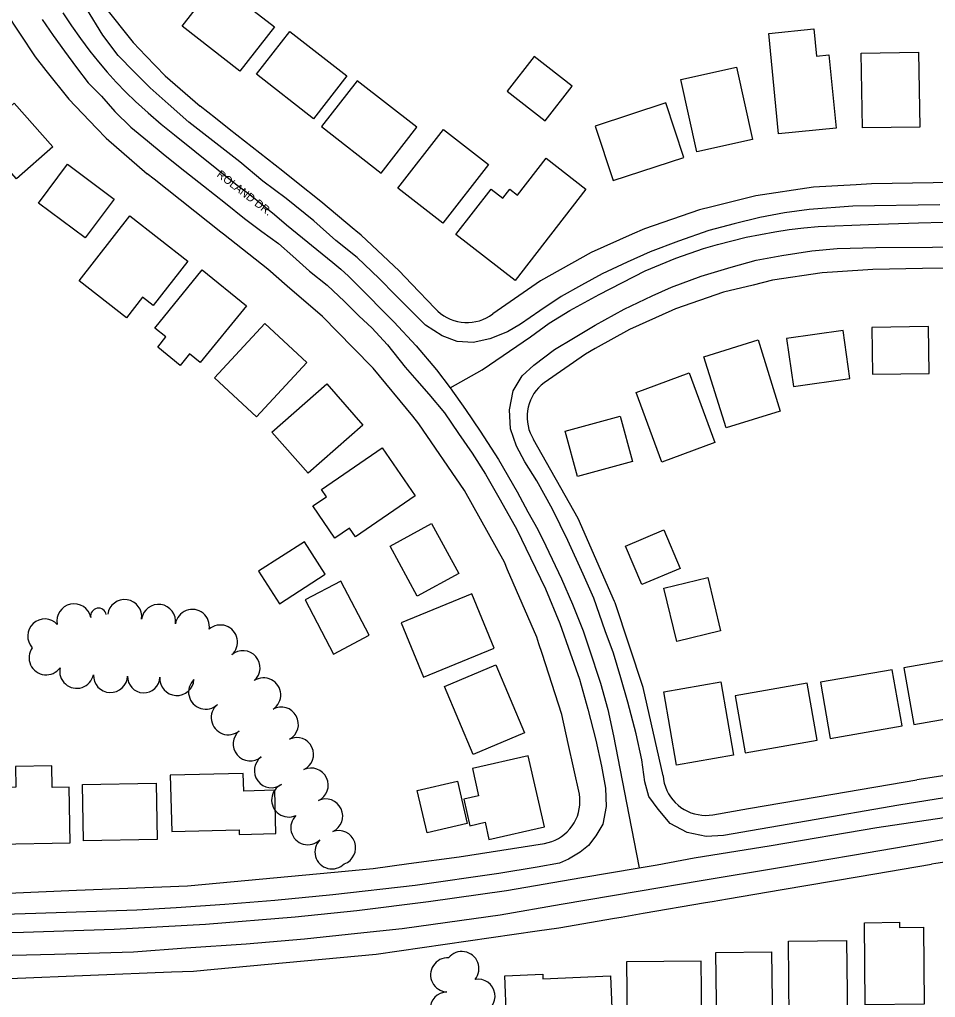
# Model space of a CAD drawing. Extents: x -2233 to 187241, y 4582 to 150524.
# Drawn here: x 115091 to 115627, y 58418 to 58990 of the extents above; entities that cross this region are included whole.
import ezdxf

# ---------------------------------------------------------------- set-up
doc = ezdxf.new("R2010")
doc.units = 0
for name, color, linetype in [('BLDG', 7, 'Continuous'), ('GE_X_CL_2000', 7, 'Continuous'), ('ROAD', 7, 'Continuous'), ('ROAD-NAME', 7, 'Continuous'), ('RW_X_Fee_RW', 7, 'Continuous'), ('TREES', 7, 'Continuous')]:
    doc.layers.add(name, color=color, linetype=linetype)

msp = doc.modelspace()

# ---------------------------------------------------------------- linework, layer by layer
at = {"layer": 'BLDG'}
for points in [[(115239.82, 58985.62), (115219.64, 58959.69), (115185.78, 58986.06), (115205.95, 59011.98)], [(115248.89, 58983.02), (115282.32, 58956.99), (115262.8, 58931.93), (115229.38, 58957.96)], [(115555.55, 58984.46), (115557.1, 58968.53), (115564.32, 58969.23), (115568.47, 58926.41), (115534.78, 58923.14), (115529.08, 58981.89)], [(115616.75, 58970.91), (115617.49, 58927.11), (115583.95, 58926.54), (115583.2, 58970.34)], [(115376.08, 58948.07), (115398.32, 58930.75), (115414.09, 58951.02), (115391.85, 58968.32)], [(115510.2, 58962.09), (115519.51, 58919.87), (115486.94, 58912.68), (115477.63, 58954.91)], [(115267.47, 58927.32), (115302.32, 58900.18), (115323.2, 58927), (115288.34, 58954.14)], [(115087.53, 58941.08), (115110.12, 58915.54), (115088.9, 58896.76), (115066.3, 58922.29)], [(115438.09, 58895.74), (115479.48, 58909.37), (115468.98, 58941.27), (115427.59, 58927.64)], [(115365.14, 58905.14), (115338.47, 58870.86), (115312.15, 58891.36), (115338.82, 58925.63)], [(115366.69, 58890.72), (115373.49, 58885.42), (115377.65, 58890.75), (115382.07, 58887.31), (115398.85, 58908.86), (115422.16, 58890.72), (115380.64, 58837.39), (115346.1, 58864.28)], [(115118.81, 58905.33), (115146.02, 58885), (115129.05, 58862.28), (115101.84, 58882.61)], [(115189.2, 58848.73), (115168.92, 58822.69), (115162.75, 58827.5), (115153.35, 58815.43), (115125.53, 58837.08), (115155.21, 58875.2)], [(115223.43, 58822.59), (115196.44, 58789.29), (115190.07, 58794.45), (115184.61, 58787.71), (115171.54, 58798.31), (115176.39, 58804.31), (115169.96, 58809.52), (115197.55, 58843.56)], [(115258.84, 58789.4), (115229.37, 58757.62), (115204.74, 58780.45), (115234.21, 58812.23)], [(115589.88, 58782.46), (115623.03, 58783.02), (115622.56, 58810.49), (115589.41, 58809.92)], [(115543.51, 58775.3), (115576.57, 58780.01), (115572.57, 58808.12), (115539.51, 58803.42)], [(115522.93, 58802.64), (115535.87, 58760.98), (115504.1, 58751.12), (115491.17, 58792.78)], [(115482.47, 58783.33), (115497.53, 58742.49), (115466.54, 58731.07), (115451.48, 58771.9)], [(115291.66, 58752.75), (115259.61, 58724.56), (115238.42, 58748.66), (115270.47, 58776.85)], [(115449.37, 58731.5), (115417.25, 58722.66), (115409.96, 58749.13), (115442.09, 58757.97)], [(115322.18, 58711.37), (115287.28, 58687.48), (115283.8, 58692.55), (115275.28, 58686.72), (115262.43, 58705.48), (115270.32, 58710.88), (115267.39, 58715.16), (115302.94, 58739.49)], [(115331.84, 58695.2), (115347.79, 58665.92), (115323.46, 58652.66), (115307.51, 58681.95)], [(115467.72, 58691.5), (115477.29, 58668.97), (115454.86, 58659.43), (115445.28, 58681.96)], [(115242.86, 58648.3), (115269.61, 58665.5), (115257.36, 58684.55), (115230.61, 58667.36)], [(115295.3, 58629.82), (115278.7, 58661.53), (115257.77, 58650.57), (115274.38, 58618.86)], [(115493.38, 58663.54), (115500.91, 58632.35), (115475.33, 58626.18), (115467.8, 58657.35)], [(115327.11, 58605.33), (115368.39, 58622.26), (115355.38, 58653.99), (115314.11, 58637.08)], [(115614.04, 58577.71), (115656.35, 58585.13), (115650.54, 58618.26), (115608.22, 58610.84)], [(115369.43, 58612.57), (115386.19, 58572.84), (115356.09, 58560.15), (115339.34, 58599.87)], [(115565.14, 58569.45), (115607.12, 58576.82), (115601.35, 58609.68), (115559.37, 58602.31)], [(115500.99, 58602.53), (115508.48, 58559.8), (115475.17, 58553.95), (115467.67, 58596.69)], [(115515.23, 58561.09), (115557.43, 58568.5), (115551.6, 58601.74), (115509.4, 58594.34)], [(115355.67, 58551.95), (115359.32, 58535.91), (115350.73, 58533.96), (115354.27, 58518.42), (115363.12, 58520.44), (115365.41, 58510.36), (115397.82, 58517.73), (115388.34, 58559.39)], [(115120.38, 58508.44), (115119.81, 58541.05), (115109.78, 58540.88), (115109.56, 58553.4), (115088.41, 58553.03), (115088.63, 58540.9), (115077.21, 58540.7), (115077.8, 58507.69)], [(115219.18, 58516.01), (115219.25, 58513.39), (115240.78, 58513.95), (115240.12, 58539.21), (115221.92, 58538.74), (115221.65, 58549.04), (115178.89, 58547.93), (115179.75, 58514.99)], [(115127.48, 58542.57), (115170.68, 58543.34), (115171.27, 58510.32), (115128.06, 58509.56)], [(115346.91, 58544.52), (115352.61, 58519.69), (115329.15, 58514.31), (115323.46, 58539.13)], [(115605.58, 58461.94), (115605.62, 58458.88), (115619.62, 58459.02), (115620.11, 58414.03), (115585.62, 58413.66), (115585.1, 58461.71)], [(115574.6, 58451.33), (115575.1, 58405.8), (115571.61, 58405.76), (115571.7, 58397.2), (115552.57, 58396.99), (115552.49, 58405.82), (115541.14, 58405.7), (115540.65, 58450.96)], [(115530.8, 58444.62), (115531.26, 58401.58), (115498.68, 58401.22), (115498.22, 58444.26)], [(115446.23, 58404.35), (115490, 58404.82), (115489.63, 58439.24), (115445.86, 58438.75)], [(115374.6, 58430.6), (115396.89, 58431.57), (115397, 58428.94), (115436.49, 58430.64), (115437.9, 58397.63), (115394.31, 58395.76), (115393.85, 58406.47), (115375.67, 58405.69)]]:
    msp.add_lwpolyline(points, close=True, dxfattribs=at)
at = {"layer": 'GE_X_CL_2000'}
for points in [[(115116.04, 58993.83), (115121.11, 58986.23), (115126.41, 58978.79), (115131.94, 58971.53), (115136.86, 58965.26), (115142, 58959.17), (115147.33, 58953.26), (115152.87, 58947.53), (115158.59, 58942), (115166.05, 58935.34), (115173.65, 58928.83), (115181.38, 58922.48), (115218.03, 58893.18), (115225.46, 58887.59), (115232.76, 58881.84), (115239.92, 58875.92), (115246.95, 58869.85), (115274.07, 58847.9), (115278.71, 58843.95), (115283.21, 58839.82), (115287.54, 58835.53), (115309.78, 58813.14), (115322.84, 58799.11), (115334.78, 58785.1), (115342.76, 58774.57)], [(115342.76, 58774.57), (115361.42, 58785.09), (115389.78, 58804.42), (115400.59, 58812.3), (115412.74, 58819.81), (115429.91, 58829.13), (115456.89, 58842.96), (115474.81, 58850.44), (115491, 58855.99), (115499.21, 58858.43), (115507.48, 58860.63), (115515.82, 58862.59), (115524.2, 58864.33), (115532.63, 58865.82), (115541.1, 58867.08), (115549.6, 58868.1), (115558.12, 58868.88), (115587.43, 58870.16), (115616.75, 58871.14), (115646.08, 58871.82), (115797.27, 58873.63), (115907.58, 58875.66), (115966.05, 58876.71)], [(115342.76, 58774.57), (115351.76, 58761.83), (115360.28, 58749.24), (115370.94, 58732.7), (115381.98, 58713.69), (115388.18, 58702.05), (115393.96, 58691.65), (115398.65, 58682.17), (115407.8, 58662.87), (115414.37, 58647.99), (115420.47, 58632.33), (115423.81, 58622.44), (115430.58, 58601.74), (115434.9, 58586.35), (115438.33, 58570.99), (115447.32, 58524.82), (115453.26, 58493.74)], [(115453.26, 58493.74), (115463.88, 58495.51), (115485.51, 58499.58), (115530.47, 58506.83), (115592.27, 58517.45), (115642.26, 58524.82), (115713.01, 58535.27), (115774.53, 58542.98), (115835.24, 58549.81), (115886.02, 58553.84), (115969.62, 58559.56)], [(114867.6, 58453.26), (114897.27, 58452.68), (114938.23, 58453.06), (114990.82, 58454.39), (115037.92, 58455.07), (115093.07, 58456.23), (115146.11, 58457.89), (115199.62, 58460.87), (115251.94, 58465.22), (115288.07, 58468.84), (115330.04, 58474.1), (115375.6, 58480.51), (115419.74, 58488.18), (115453.26, 58493.74)]]:
    msp.add_lwpolyline(points, dxfattribs=at)
at = {"layer": 'ROAD'}
for points in [[(115629.2, 58881.65), (115578.25, 58880.79), (115552.66, 58878.82), (115538.38, 58876.97), (115523.8, 58874.11), (115508.96, 58870.5), (115494.12, 58866.64), (115476.22, 58860.41), (115459.81, 58854.05), (115446.28, 58848.06), (115431.69, 58841.2), (115419.54, 58834.7), (115407.64, 58827.97), (115395.11, 58819.54), (115383.9, 58811.73), (115376.32, 58807.23), (115365.92, 58803.24), (115356.22, 58801), (115346.7, 58801.64), (115338.01, 58804.91), (115328.19, 58811.18), (115319.5, 58819.89), (115310.7, 58828.66), (115301.2, 58838.57), (115288.25, 58850.73), (115275.82, 58860.82), (115262.88, 58872.16), (115246.75, 58885.27), (115233, 58895.36), (115219.68, 58906.65), (115203.86, 58919.06), (115189.68, 58929.85), (115177.62, 58940.69), (115167.17, 58949.97), (115157.74, 58959.37), (115148.37, 58968.96), (115139.55, 58980.74), (115129.88, 58996.4)], [(115103.96, 58989.99), (115110.45, 58980.6), (115116.95, 58971.44), (115123.95, 58961.99), (115130.88, 58952.91), (115138.69, 58945.13), (115146.5, 58936.11), (115155.87, 58926.95), (115165.56, 58919.06), (115174.82, 58911.35), (115184.7, 58903.51), (115198.32, 58892.79), (115211.2, 58882.56), (115222.33, 58873.66), (115232.52, 58866.08), (115242.15, 58858.99), (115250.65, 58851.54), (115260.46, 58842.82), (115270.65, 58834.67), (115280.78, 58825.08), (115289.4, 58816.55), (115296.9, 58809.66), (115305.96, 58799.7), (115316.39, 58786.73), (115323.2, 58778.9), (115330.26, 58770.87), (115339.45, 58759.91), (115347.63, 58747.94), (115355.63, 58736.29), (115363.43, 58724.14), (115372.04, 58709.04), (115381.66, 58691.62), (115389.77, 58675.15), (115398.38, 58657), (115406.93, 58636.7), (115412.97, 58619.54), (115418.33, 58604.08), (115423.18, 58586.68), (115427.85, 58568.46), (115431.34, 58553.24), (115433.64, 58540.35), (115433.93, 58529.64), (115431.98, 58519.33), (115427.9, 58512.57), (115423.64, 58506.88), (115418.74, 58502.88), (115411.98, 58498.95), (115406.6, 58496.51), (115393.64, 58494.16), (115371.1, 58490.49), (115322.21, 58483.5), (115274.02, 58478), (115240.15, 58474.79), (115210.86, 58472.27), (115182.45, 58470.49), (115159.29, 58468.97), (115100.33, 58467.17), (115043.88, 58465.37)], [(115652.68, 58538.15), (115605.16, 58530.4), (115551.14, 58521.1), (115502.56, 58512.77), (115492.49, 58512.04), (115481.42, 58514.44), (115471.41, 58519.83), (115464.35, 58528.04), (115458.91, 58535.62), (115456.61, 58544.07), (115454.87, 58557.03), (115451.51, 58572.12), (115446.66, 58590.71), (115442.48, 58604.99), (115438.19, 58619.38), (115433.39, 58632.47), (115426.66, 58651.45), (115420.55, 58665.54), (115411.62, 58685.33), (115402.51, 58703.62), (115393.47, 58720.21), (115386.41, 58731.24), (115381.48, 58740.44), (115377.92, 58750.65), (115377.37, 58761.67), (115379.58, 58772.74), (115384.85, 58781.5), (115391.56, 58787.8), (115403.72, 58797.05), (115414.8, 58803.67), (115427.51, 58811.22), (115444.42, 58820.47), (115460.96, 58828.32), (115472.23, 58833.44), (115489.64, 58839.86), (115507.11, 58845.09), (115521.7, 58849.2), (115536.72, 58851.99), (115554.31, 58854.67), (115569.15, 58856.08), (115591.86, 58856.67), (115624.97, 58856.81), (115691.12, 58858.28)], [(115005.26, 58441.05), (115029.33, 58441.42), (115111.18, 58443.37), (115157.37, 58444.75), (115188.04, 58447.02), (115223.28, 58449.4), (115257.46, 58452.3), (115288.56, 58455.5), (115314.61, 58458.35), (115341.21, 58462), (115372.01, 58466.28), (115407.57, 58472.61), (115452.63, 58480.12), (115489.63, 58486.32), (115536.58, 58494.27), (115578.21, 58501.15), (115618.15, 58508.1), (115652.7, 58514.31)]]:
    msp.add_lwpolyline(points, dxfattribs=at)
at = {"layer": 'RW_X_Fee_RW'}
msp.add_line((115169.44, 58896.51), (115165.38, 58899.72), dxfattribs=at)
for points in [[(115084.9, 59148.64), (115088.21, 59121.72), (115093.98, 59095.22), (115102.15, 59069.37), (115112.64, 59044.36), (115113.68, 59042.42), (115125.39, 59020.43), (115140.27, 58997.76), (115157.16, 58976.54), (115164.68, 58968.7), (115175.92, 58956.96), (115196.46, 58939.24)], [(115035.05, 59144.45), (115036.43, 59133.27), (115037.53, 59124.34), (115038.93, 59113.01), (115045.02, 59085.07), (115045.68, 59082.04), (115046.25, 59080.22), (115055.23, 59051.83), (115059.96, 59040.55), (115061.12, 59037.79), (115067.5, 59022.62), (115080.92, 58997.41), (115082.39, 58994.65), (115099.79, 58968.16), (115106.15, 58960.17), (115119.53, 58943.37), (115135.81, 58926.39), (115141.45, 58920.5), (115165.38, 58899.72)], [(115267.11, 58883.47), (115252.69, 58894.87), (115244.69, 58901.2), (115213.47, 58925.89), (115205.47, 58932.22), (115196.46, 58939.24)], [(115235.98, 58843.89), (115210.12, 58864.34), (115208.55, 58865.58), (115169.44, 58896.51)], [(115914.52, 58898.28), (115895.27, 58898.14), (115850.27, 58897.51), (115805.28, 58896.88), (115760.28, 58896.25), (115715.28, 58895.62), (115670.29, 58894.99), (115625.29, 58894.36), (115589.22, 58893.86)], [(115589.22, 58893.86), (115580.35, 58893.33), (115555.25, 58891.84), (115521.6, 58886.77), (115492.62, 58879.67), (115491.65, 58879.43), (115488.54, 58878.67), (115456.35, 58867.62), (115449.28, 58864.45), (115425.29, 58853.71), (115395.62, 58837.05), (115367.57, 58817.77)], [(115333.94, 58820.94), (115320.11, 58835.4), (115312.84, 58843.01), (115290.53, 58863.88), (115287.53, 58866.39), (115286.61, 58867.16), (115267.11, 58883.47)], [(115324.43, 58753.59), (115320.77, 58758.02), (115297.54, 58786.15), (115286, 58797.93), (115267.98, 58816.32), (115247.36, 58834.09), (115235.98, 58843.89)], [(115589.92, 58843.74), (115569.3, 58842.39), (115560.45, 58841.86), (115531.25, 58837.46), (115519.98, 58834.69), (115502.57, 58830.43), (115474.64, 58820.83), (115472.32, 58819.79), (115447.69, 58808.75), (115427.62, 58797.48), (115421.95, 58794.29), (115397.62, 58777.55)], [(115915.22, 58848.29), (115894.13, 58848.12), (115849.13, 58847.49), (115804.14, 58846.86), (115759.14, 58846.23), (115714.14, 58845.6), (115669.15, 58844.97), (115619.15, 58844.27), (115589.92, 58843.74)], [(115333.94, 58820.94), (115335.47, 58819.39), (115337.13, 58817.97), (115338.91, 58816.71), (115340.79, 58815.61), (115342.76, 58814.67), (115344.81, 58813.91), (115346.91, 58813.33), (115349.06, 58812.94), (115351.23, 58812.74), (115353.41, 58812.72), (115355.58, 58812.9), (115357.73, 58813.26), (115359.84, 58813.81), (115361.9, 58814.55), (115363.88, 58815.45), (115365.78, 58816.53), (115367.57, 58817.77)], [(115397.62, 58777.55), (115395.94, 58776.16), (115394.39, 58774.63), (115392.97, 58772.97), (115391.71, 58771.19), (115390.61, 58769.31), (115389.67, 58767.34), (115388.91, 58765.29), (115388.33, 58763.19), (115387.94, 58761.04), (115387.74, 58758.87), (115387.72, 58756.69), (115387.9, 58754.52), (115388.26, 58752.37), (115388.81, 58750.26), (115389.54, 58748.2), (115390.45, 58746.22), (115391.53, 58744.32)], [(115418.3, 58536.94), (115411.78, 58566.44), (115408.02, 58583.46), (115396.48, 58619.09), (115394.63, 58624.79), (115393.34, 58628.8), (115376.33, 58668.05), (115374.39, 58672.53), (115351.17, 58714.52), (115324.43, 58753.59)], [(115467.24, 58547.55), (115455.53, 58599.26), (115439.18, 58648.8), (115438.92, 58649.6), (115417.51, 58698.11), (115391.53, 58744.32)], [(115913.81, 58580.45), (115814.11, 58572.16), (115714.75, 58560.45), (115615.85, 58545.31)], [(115467.24, 58547.55), (115467.54, 58545.38), (115467.99, 58543.24), (115468.64, 58541.15), (115469.46, 58539.12), (115470.46, 58537.18), (115471.62, 58535.32), (115472.94, 58533.58), (115474.41, 58531.96), (115476.02, 58530.47), (115477.74, 58529.13), (115479.58, 58527.94), (115481.51, 58526.92), (115483.53, 58526.07), (115485.61, 58525.4), (115487.75, 58524.91), (115489.91, 58524.62), (115492.1, 58524.51), (115494.28, 58524.59), (115496.45, 58524.89)], [(115496.45, 58524.89), (115517.3, 58528.48), (115566.58, 58536.89), (115615.85, 58545.31)], [(115397.87, 58508.08), (115400, 58508.54), (115402.09, 58509.19), (115404.11, 58510.01), (115406.05, 58511.01), (115407.89, 58512.17), (115409.63, 58513.49), (115411.25, 58514.96), (115412.73, 58516.56), (115414.07, 58518.28), (115415.25, 58520.12), (115416.27, 58522.05), (115417.11, 58524.06), (115417.78, 58526.14), (115418.26, 58528.27), (115418.56, 58530.43), (115418.66, 58532.61), (115418.58, 58534.79), (115418.3, 58536.94)], [(115967.87, 58533.44), (115941.8, 58531.66), (115896.81, 58528.6), (115852.86, 58525.6), (115851.83, 58525.49), (115806.85, 58520.59), (115761.88, 58515.7), (115738.26, 58513.13), (115716.9, 58509.92), (115671.94, 58503.17), (115626.97, 58496.43), (115624.27, 58496.02)], [(115275.03, 58491.18), (115297.72, 58493.51), (115318.51, 58496.28), (115347.89, 58500.18), (115397.87, 58508.08)], [(115504.89, 58475.64), (115537.04, 58481.13), (115582.01, 58488.81), (115624.27, 58496.02)], [(115084.02, 58479.03), (115124, 58480.67), (115173.96, 58482.73), (115189.08, 58483.35), (115275.03, 58491.18)], [(115455.6, 58467.22), (115492.09, 58473.45), (115496.08, 58474.13), (115504.89, 58475.64)], [(115406.32, 58458.8), (115438.83, 58464.35), (115442.8, 58465.03), (115455.6, 58467.22)], [(115084.79, 58429.04), (115179.71, 58432.94), (115192.43, 58433.46), (115204.62, 58434.59), (115299.42, 58443.37), (115393.52, 58456.95), (115406.32, 58458.8)]]:
    msp.add_lwpolyline(points, dxfattribs=at)
at = {"layer": 'TREES'}
for centre, radius, start, end in [((115122.61, 58638.24), 10, 11.9758, 191.9758), ((115152.23, 58640.7), 10, 352.012, 172.012), ((115136.92, 58641.12), 4.59, 10.1659, 190.1659), ((115172.04, 58637.92), 10, 352.012, 172.012), ((115191.81, 58634.94), 10, 350.8212, 170.8212), ((115105.5, 58629.36), 10, 42.8987, 222.8987), ((115208.29, 58625.84), 10, 311.3437, 131.3437), ((115106.29, 58616.69), 10, 144.1548, 324.1548), ((115221.48, 58610.81), 10, 311.2207, 131.2207), ((115124.18, 58608.79), 10, 168.2019, 348.2019), ((115143.96, 58606.36), 10, 177.7978, 357.7978), ((115163.39, 58605.62), 9.44, 177.7978, 357.7978), ((115182.8, 58604.58), 10, 176.1516, 356.1516), ((115199.62, 58596.62), 10, 133.1795, 313.1795), ((115233.56, 58594.93), 10, 303.3098, 123.3098), ((115212.88, 58581.65), 10, 129.8842, 309.8842), ((115243.9, 58577.82), 10, 298.9571, 118.9571), ((115225.71, 58566.31), 10, 129.9018, 309.9018), ((115252.92, 58560.16), 9.84, 295.1073, 115.1073), ((115238.1, 58550.62), 10, 126.7139, 306.7139), ((115261.34, 58542.19), 10, 295.1073, 115.1073), ((115248.23, 58533.51), 10, 114.5563, 294.5563), ((115269.82, 58524.08), 10, 295.1073, 115.1073), ((115259.42, 58517.3), 10, 134.6422, 314.6422), ((115277.38, 58505.59), 10, 289.3653, 109.3653), ((115273.57, 58503.17), 10, 135.4587, 315.4587), ((115349.55, 58434.87), 10, 320.9447, 140.9447), ((115341.25, 58431.19), 10, 86.9451, 266.9451), ((115358.97, 58418.71), 10, 279.5167, 99.5167), ((115340.97, 58411.21), 10, 91.4142, 271.4142)]:
    msp.add_arc(centre, radius, start, end, dxfattribs=at)

# ---------------------------------------------------------------- texts
at = {"layer": 'ROAD-NAME'}
msp.add_text('ROLAND DR.', height=4.68, rotation=322.309, dxfattribs=at).set_placement((115205.75, 58898.55))

doc.saveas('drawing.dxf')
